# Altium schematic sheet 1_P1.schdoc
size 612 x 312 mm; Symbol: Sheet-Symbol_A4; Device: Sheet-Symbol_A4; @Project Name: TG-U1; Reviewed: EasyEDA; Part Number: JLCPCB-002; Drawn: EasyEDA; @Page Count: 1; @Update Date: 2024-12-23; @Create Date: 2024-12-20; @Schematic Name: Schematic1; @Page No: 1; @Page Name: P1; Company: EasyEDA.com; Version: V0.1; Page Size: A4; @Create Time: 16:03:04; @Update Time: 22:39:37; Title Block Position: 3; Width: 2362.2047244094488; Height: 1181.1023622047244; Region Start: 1; X Region Count: 6; Y Region Count: 4; Color: #660000; Blade Width: 10; @Board Name: Board1
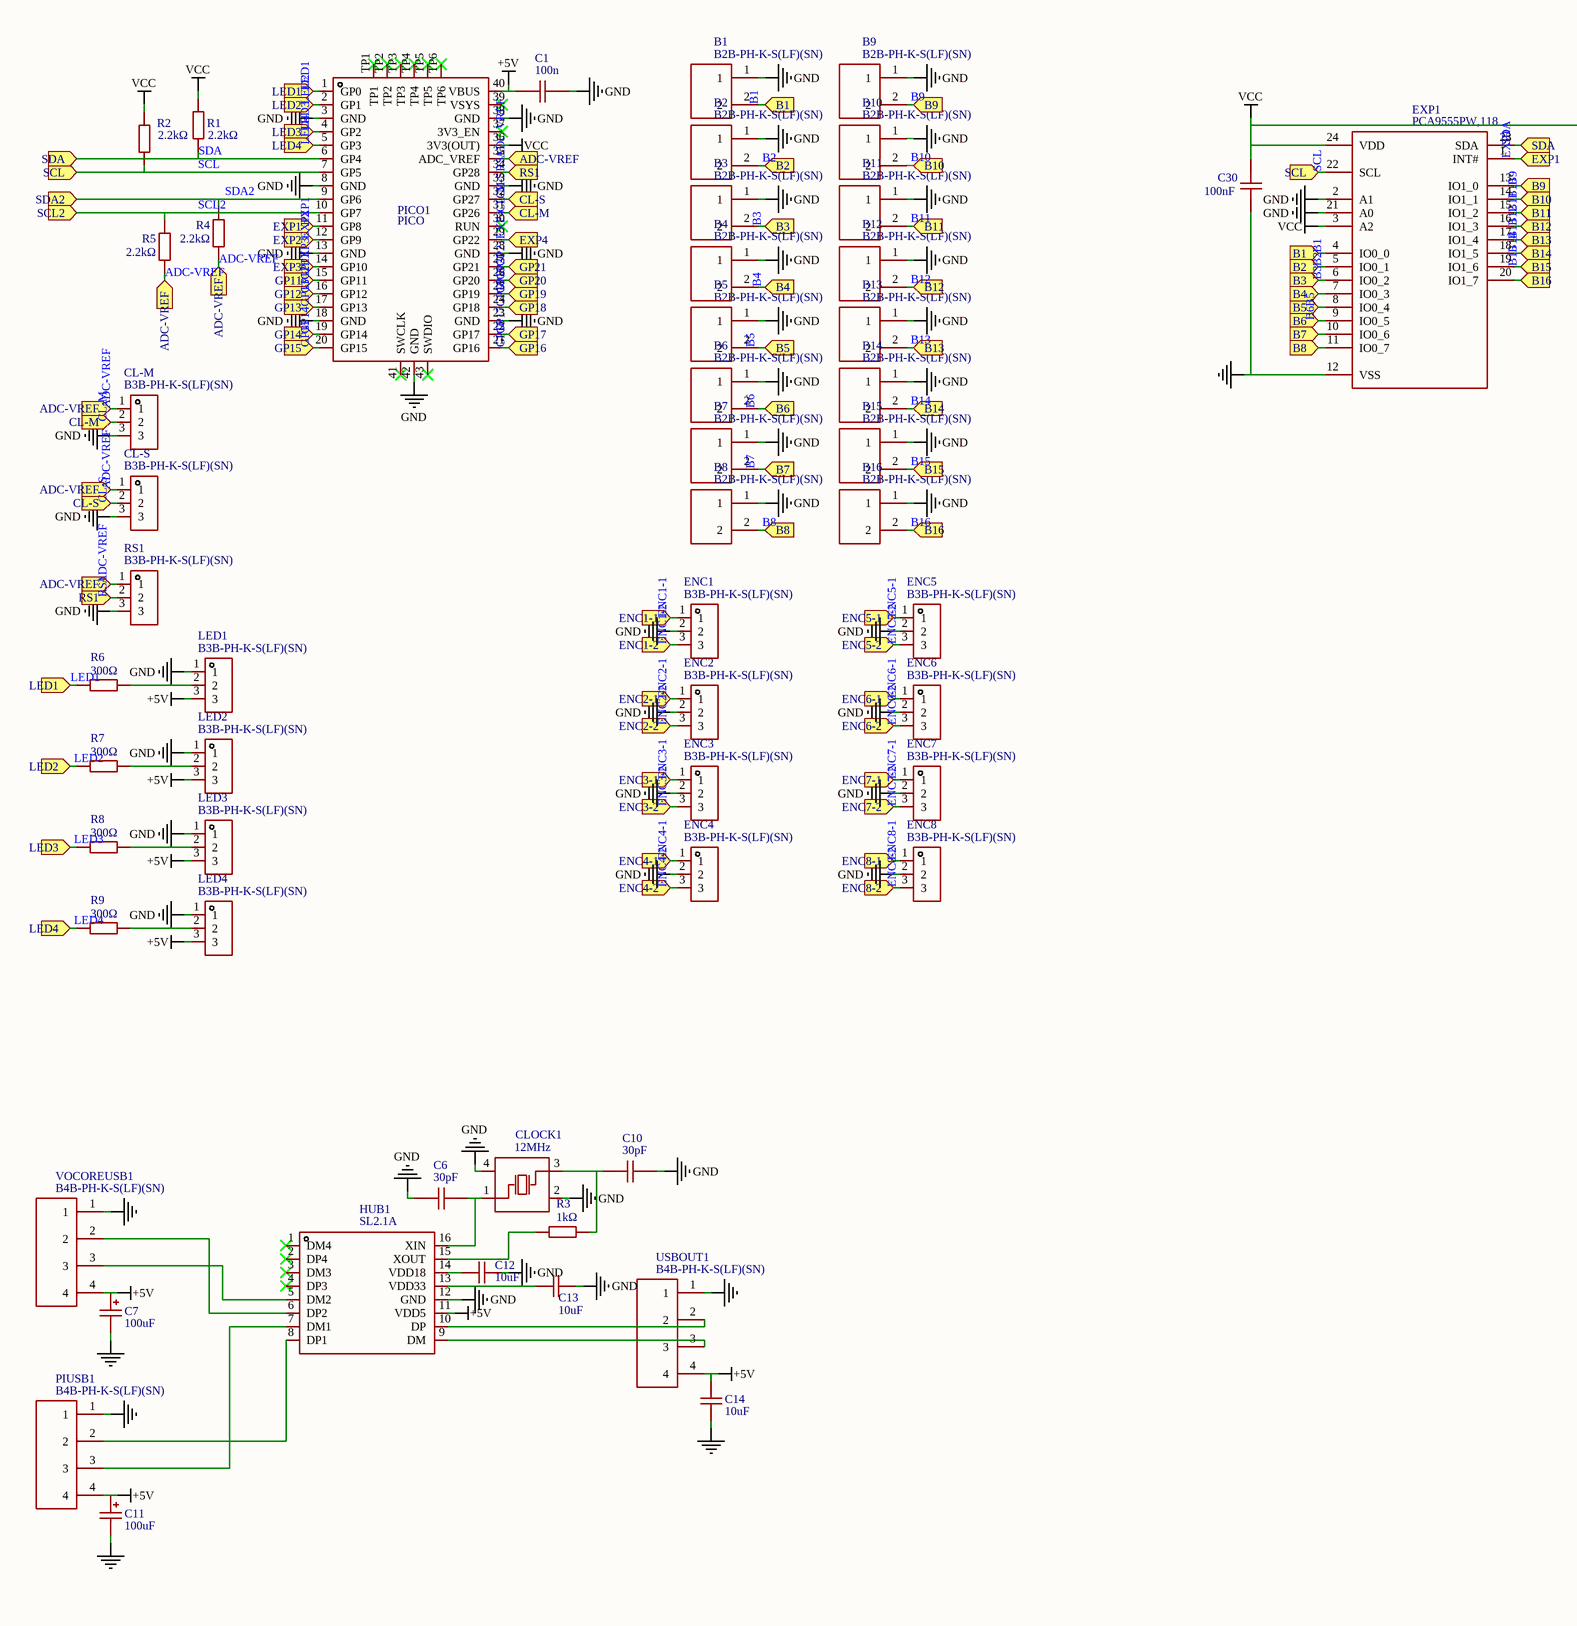
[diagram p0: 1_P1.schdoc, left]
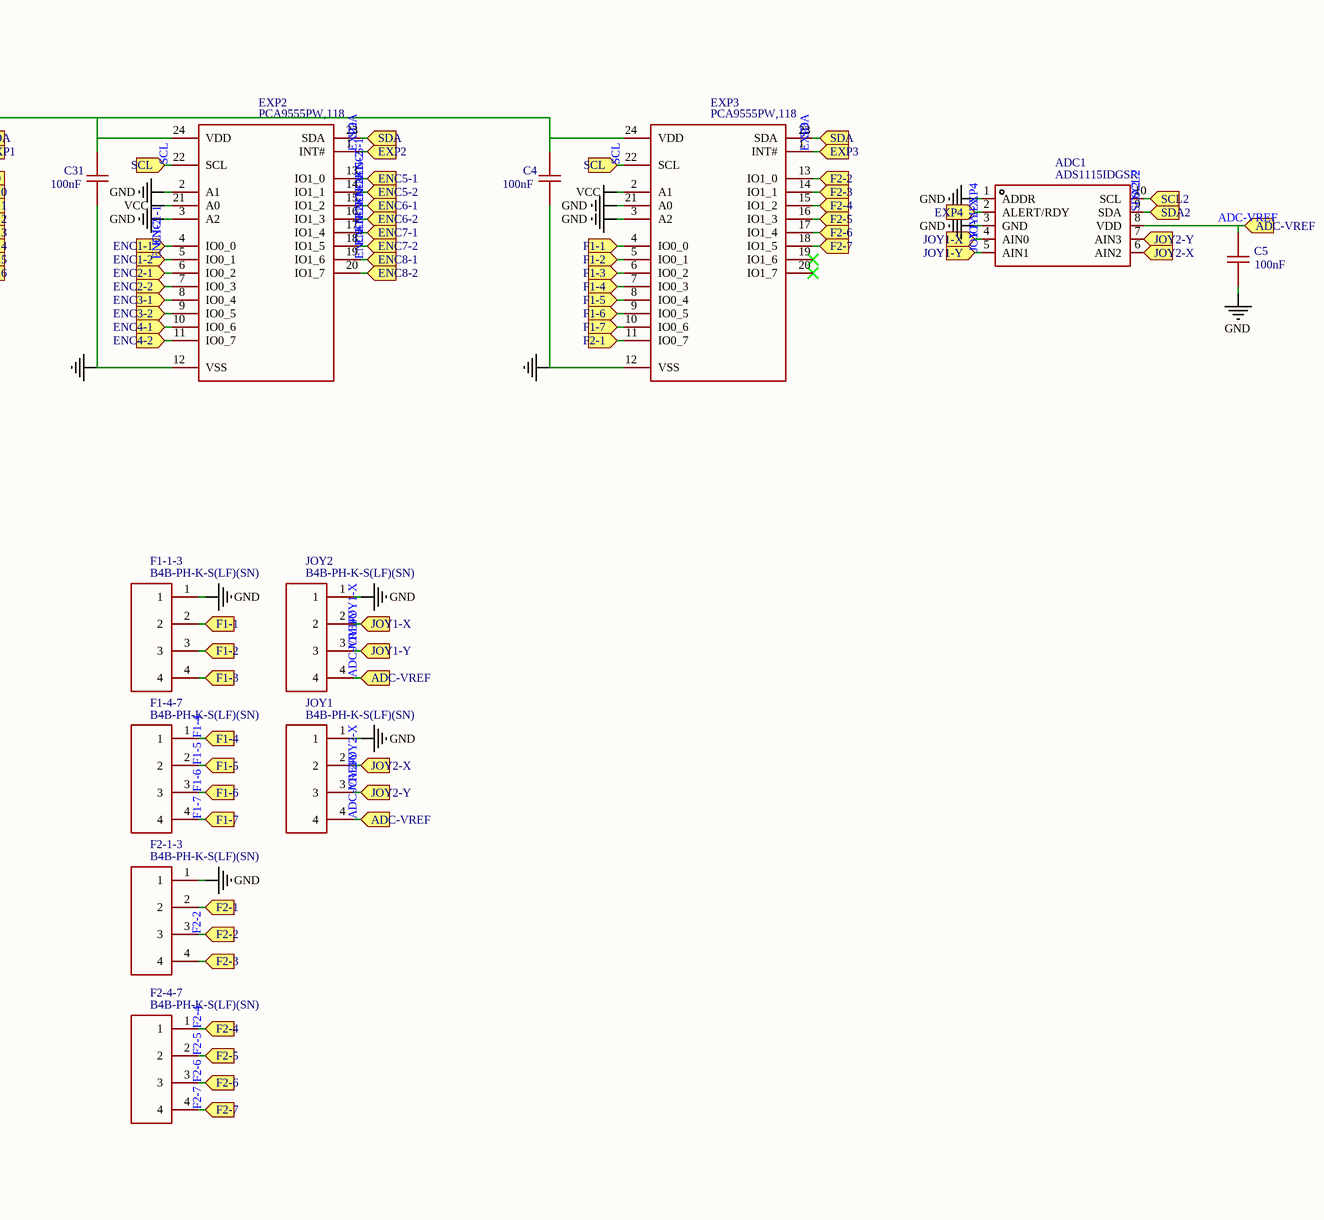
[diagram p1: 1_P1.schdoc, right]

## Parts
ADC1  ADS1115IDGSR  [MSOP-10_L3.0-W3.0-P0.50-LS5.0-BL]  (value not drawn)
B1  B2B-PH-K-S(LF)(SN)  [CONN-TH_B2B-PH-K-S]  (value not drawn)
B2  B2B-PH-K-S(LF)(SN)  [CONN-TH_B2B-PH-K-S]  (value not drawn)
B3  B2B-PH-K-S(LF)(SN)  [CONN-TH_B2B-PH-K-S]  (value not drawn)
B4  B2B-PH-K-S(LF)(SN)  [CONN-TH_B2B-PH-K-S]  (value not drawn)
B5  B2B-PH-K-S(LF)(SN)  [CONN-TH_B2B-PH-K-S]  (value not drawn)
B6  B2B-PH-K-S(LF)(SN)  [CONN-TH_B2B-PH-K-S]  (value not drawn)
B7  B2B-PH-K-S(LF)(SN)  [CONN-TH_B2B-PH-K-S]  (value not drawn)
B8  B2B-PH-K-S(LF)(SN)  [CONN-TH_B2B-PH-K-S]  (value not drawn)
B9  B2B-PH-K-S(LF)(SN)  [CONN-TH_B2B-PH-K-S]  (value not drawn)
B10  B2B-PH-K-S(LF)(SN)  [CONN-TH_B2B-PH-K-S]  (value not drawn)
B11  B2B-PH-K-S(LF)(SN)  [CONN-TH_B2B-PH-K-S]  (value not drawn)
B12  B2B-PH-K-S(LF)(SN)  [CONN-TH_B2B-PH-K-S]  (value not drawn)
B13  B2B-PH-K-S(LF)(SN)  [CONN-TH_B2B-PH-K-S]  (value not drawn)
B14  B2B-PH-K-S(LF)(SN)  [CONN-TH_B2B-PH-K-S]  (value not drawn)
B15  B2B-PH-K-S(LF)(SN)  [CONN-TH_B2B-PH-K-S]  (value not drawn)
B16  B2B-PH-K-S(LF)(SN)  [CONN-TH_B2B-PH-K-S]  (value not drawn)
C1  100n  [C0603]  (value not drawn)
C4  100nF  [C0603]  (value not drawn)
C5  100nF  [C0603]  (value not drawn)
C6  30pF  [C0603]  (value not drawn)
C7  100uF  [CAP-SMD_L3.5-W2.8]  (value not drawn)
C10  30pF  [C0603]  (value not drawn)
C11  100uF  [CAP-SMD_L3.5-W2.8]  (value not drawn)
C12  10uF  [C0402]  (value not drawn)
C13  10uF  [C0402]  (value not drawn)
C14  10uF  [C0402]  (value not drawn)
C30  100nF  [C0603]  (value not drawn)
C31  100nF  [C0603]  (value not drawn)
CL-M  B3B-PH-K-S(LF)(SN)  [CONN-TH_B3B-PH-K-S]  (value not drawn)
CL-S  B3B-PH-K-S(LF)(SN)  [CONN-TH_B3B-PH-K-S]  (value not drawn)
CLOCK1  12MHz  [OSC-SMD_4P-L3.2-W2.5-BL]  (value not drawn)
ENC1  B3B-PH-K-S(LF)(SN)  [CONN-TH_B3B-PH-K-S]  (value not drawn)
ENC2  B3B-PH-K-S(LF)(SN)  [CONN-TH_B3B-PH-K-S]  (value not drawn)
ENC3  B3B-PH-K-S(LF)(SN)  [CONN-TH_B3B-PH-K-S]  (value not drawn)
ENC4  B3B-PH-K-S(LF)(SN)  [CONN-TH_B3B-PH-K-S]  (value not drawn)
ENC5  B3B-PH-K-S(LF)(SN)  [CONN-TH_B3B-PH-K-S]  (value not drawn)
ENC6  B3B-PH-K-S(LF)(SN)  [CONN-TH_B3B-PH-K-S]  (value not drawn)
ENC7  B3B-PH-K-S(LF)(SN)  [CONN-TH_B3B-PH-K-S]  (value not drawn)
ENC8  B3B-PH-K-S(LF)(SN)  [CONN-TH_B3B-PH-K-S]  (value not drawn)
EXP1  PCA9555PW,118  [TSSOP-24_L7.8-W4.4-P0.65-LS6.4-BL]  (value not drawn)
EXP2  PCA9555PW,118  [TSSOP-24_L7.8-W4.4-P0.65-LS6.4-BL]  (value not drawn)
EXP3  PCA9555PW,118  [TSSOP-24_L7.8-W4.4-P0.65-LS6.4-BL]  (value not drawn)
F1-1-3  B4B-PH-K-S(LF)(SN)  [CONN-TH_B4B-PH-K-S]  (value not drawn)
F1-4-7  B4B-PH-K-S(LF)(SN)  [CONN-TH_B4B-PH-K-S]  (value not drawn)
F2-1-3  B4B-PH-K-S(LF)(SN)  [CONN-TH_B4B-PH-K-S]  (value not drawn)
F2-4-7  B4B-PH-K-S(LF)(SN)  [CONN-TH_B4B-PH-K-S]  (value not drawn)
HUB1  SL2.1A  [SOP-16_L10.0-W3.9-P1.27-LS6.0-BL]  (value not drawn)
JOY1  B4B-PH-K-S(LF)(SN)  [CONN-TH_B4B-PH-K-S]  (value not drawn)
JOY2  B4B-PH-K-S(LF)(SN)  [CONN-TH_B4B-PH-K-S]  (value not drawn)
LED1  B3B-PH-K-S(LF)(SN)  [CONN-TH_B3B-PH-K-S]  (value not drawn)
LED2  B3B-PH-K-S(LF)(SN)  [CONN-TH_B3B-PH-K-S]  (value not drawn)
LED3  B3B-PH-K-S(LF)(SN)  [CONN-TH_B3B-PH-K-S]  (value not drawn)
LED4  B3B-PH-K-S(LF)(SN)  [CONN-TH_B3B-PH-K-S]  (value not drawn)
PICO1  PICO  [COMM-SMD_L51.0-W21.0-P2.54_SC0916]  (value not drawn)
PIUSB1  B4B-PH-K-S(LF)(SN)  [CONN-TH_B4B-PH-K-S]  (value not drawn)
R1  2.2kΩ  [R0402]  (value not drawn)
R2  2.2kΩ  [R0402]  (value not drawn)
R3  1kΩ  [R0805]  (value not drawn)
R4  2.2kΩ  [R0402]  (value not drawn)
R5  2.2kΩ  [R0402]  (value not drawn)
R6  300Ω  [R0402]  (value not drawn)
R7  300Ω  [R0402]  (value not drawn)
R8  300Ω  [R0402]  (value not drawn)
R9  300Ω  [R0402]  (value not drawn)
RS1  B3B-PH-K-S(LF)(SN)  [CONN-TH_B3B-PH-K-S]  (value not drawn)
USBOUT1  B4B-PH-K-S(LF)(SN)  [CONN-TH_B4B-PH-K-S]  (value not drawn)
VOCOREUSB1  B4B-PH-K-S(LF)(SN)  [CONN-TH_B4B-PH-K-S]  (value not drawn)

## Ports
ADC-VREF (in), B1 (in), B2 (in), B3 (in), B4 (in), B5 (in), B6 (in), B7 (in), B8 (in), B9 (in), B10 (in), B11 (in), B12 (in), B13 (in), B14 (in), B15 (in), B16 (in), CL-M (in), CL-S (in), ENC1-1 (in), ENC1-2 (in), ENC2-1 (in), ENC2-2 (in), ENC3-1 (in), ENC3-2 (in), ENC4-1 (in), ENC4-2 (in), ENC5-1 (in), ENC5-2 (in), ENC6-1 (in), ENC6-2 (in), ENC7-1 (in), ENC7-2 (in), ENC8-1 (in), ENC8-2 (in), EXP1 (in), EXP2 (in), EXP3 (in), EXP4 (in), F1-1 (in), F1-2 (in), F1-3 (in), F1-4 (in), F1-5 (in), F1-6 (in), F1-7 (in), F2-1 (in), F2-2 (in), F2-3 (in), F2-4 (in), F2-5 (in), F2-6 (in), F2-7 (in), GP11 (in), GP12 (in), GP13 (in), GP14 (in), GP15 (in), GP16 (in), GP17 (in), GP18 (in), GP19 (in), GP20 (in), GP21 (in), JOY1-X (in), JOY1-Y (in), JOY2-X (in), JOY2-Y (in), LED1 (in), LED2 (in), LED3 (in), LED4 (in), RS1 (in), SCL2 (in), SCL (in), SDA2 (in), SDA (in)

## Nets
+5V: C1.2 C7.1 C11.1 C14.1 HUB1.11(VDD5) LED1.3 LED2.3 LED3.3 LED4.3 PICO1.40(VBUS) PIUSB1.4 USBOUT1.4 VOCOREUSB1.4
GND: ADC1.1(ADDR) ADC1.3(GND) B1.1 B2.1 B3.1 B4.1 B5.1 B6.1 B7.1 B8.1 B9.1 B10.1 B11.1 B12.1 B13.1 B14.1 B15.1 B16.1 C1.1 C4.1 C5.1 C6.1 C7.2 C10.2 C11.2 C12.2 C13.2 C14.2 C30.1 C31.1 CL-M.3 CL-S.3 CLOCK1.2(GND) CLOCK1.4(GND) ENC1.2 ENC2.2 ENC3.2 ENC4.2 ENC5.2 ENC6.2 ENC7.2 ENC8.2 EXP1.2(A1) EXP1.12(VSS) EXP1.21(A0) EXP2.2(A1) EXP2.3(A2) EXP2.12(VSS) EXP3.3(A2) EXP3.12(VSS) EXP3.21(A0) F1-1-3.1 F2-1-3.1 HUB1.12(GND) JOY1.1 JOY2.1 LED1.1 LED2.1 LED3.1 LED4.1 PICO1.3(GND) PICO1.8(GND) PICO1.13(GND) PICO1.18(GND) PICO1.23(GND) PICO1.28(GND) PICO1.33(GND) PICO1.38(GND) PICO1.42(GND) PIUSB1.1 RS1.3 USBOUT1.1 VOCOREUSB1.1
VCC: C4.2 C30.2 C31.2 EXP1.3(A2) EXP1.24(VDD) EXP2.21(A0) EXP2.24(VDD) EXP3.2(A1) EXP3.24(VDD) PICO1.36(3V3(OUT)) R1.1 R2.1
ADC-VREF: ADC1.8(VDD) C5.2 CL-M.1 CL-S.1 JOY1.4 JOY2.4 PICO1.35(ADC_VREF) R4.2 R5.2 RS1.1 ; port ADC-VREF
B1: B1.2 EXP1.4(IO0_0) ; port B1
B2: B2.2 EXP1.5(IO0_1) ; port B2
B3: B3.2 EXP1.6(IO0_2) ; port B3
B4: B4.2 EXP1.7(IO0_3) ; port B4
B5: B5.2 EXP1.8(IO0_4) ; port B5
B6: B6.2 EXP1.9(IO0_5) ; port B6
B7: B7.2 EXP1.10(IO0_6) ; port B7
B8: B8.2 EXP1.11(IO0_7) ; port B8
B9: B9.2 EXP1.13(IO1_0) ; port B9
B10: B10.2 EXP1.14(IO1_1) ; port B10
B11: B11.2 EXP1.15(IO1_2) ; port B11
B12: B12.2 EXP1.16(IO1_3) ; port B12
B13: B13.2 EXP1.17(IO1_4) ; port B13
B14: B14.2 EXP1.18(IO1_5) ; port B14
B15: B15.2 EXP1.19(IO1_6) ; port B15
B16: B16.2 EXP1.20(IO1_7) ; port B16
CL-M: CL-M.2 PICO1.31(GP26) ; port CL-M
CL-S: CL-S.2 PICO1.32(GP27) ; port CL-S
ENC1-1: ENC1.1 EXP2.4(IO0_0) ; port ENC1-1
ENC1-2: ENC1.3 EXP2.5(IO0_1) ; port ENC1-2
ENC2-1: ENC2.1 EXP2.6(IO0_2) ; port ENC2-1
ENC2-2: ENC2.3 EXP2.7(IO0_3) ; port ENC2-2
ENC3-1: ENC3.1 EXP2.8(IO0_4) ; port ENC3-1
ENC3-2: ENC3.3 EXP2.9(IO0_5) ; port ENC3-2
ENC4-1: ENC4.1 EXP2.10(IO0_6) ; port ENC4-1
ENC4-2: ENC4.3 EXP2.11(IO0_7) ; port ENC4-2
ENC5-1: ENC5.1 EXP2.13(IO1_0) ; port ENC5-1
ENC5-2: ENC5.3 EXP2.14(IO1_1) ; port ENC5-2
ENC6-1: ENC6.1 EXP2.15(IO1_2) ; port ENC6-1
ENC6-2: ENC6.3 EXP2.16(IO1_3) ; port ENC6-2
ENC7-1: ENC7.1 EXP2.17(IO1_4) ; port ENC7-1
ENC7-2: ENC7.3 EXP2.18(IO1_5) ; port ENC7-2
ENC8-1: ENC8.1 EXP2.19(IO1_6) ; port ENC8-1
ENC8-2: ENC8.3 EXP2.20(IO1_7) ; port ENC8-2
EXP1: EXP1.1(INT#) PICO1.11(GP8) ; port EXP1
EXP2: EXP2.1(INT#) PICO1.12(GP9) ; port EXP2
EXP3: EXP3.1(INT#) PICO1.14(GP10) ; port EXP3
EXP4: ADC1.2(ALERT/RDY) PICO1.29(GP22) ; port EXP4
F1-1: EXP3.4(IO0_0) F1-1-3.2 ; port F1-1
F1-2: EXP3.5(IO0_1) F1-1-3.3 ; port F1-2
F1-3: EXP3.6(IO0_2) F1-1-3.4 ; port F1-3
F1-4: EXP3.7(IO0_3) F1-4-7.1 ; port F1-4
F1-5: EXP3.8(IO0_4) F1-4-7.2 ; port F1-5
F1-6: EXP3.9(IO0_5) F1-4-7.3 ; port F1-6
F1-7: EXP3.10(IO0_6) F1-4-7.4 ; port F1-7
F2-1: EXP3.11(IO0_7) F2-1-3.2 ; port F2-1
F2-2: EXP3.13(IO1_0) F2-1-3.3 ; port F2-2
F2-3: EXP3.14(IO1_1) F2-1-3.4 ; port F2-3
F2-4: EXP3.15(IO1_2) F2-4-7.1 ; port F2-4
F2-5: EXP3.16(IO1_3) F2-4-7.2 ; port F2-5
F2-6: EXP3.17(IO1_4) F2-4-7.3 ; port F2-6
F2-7: EXP3.18(IO1_5) F2-4-7.4 ; port F2-7
GP11: PICO1.15(GP11) ; port GP11
GP12: PICO1.16(GP12) ; port GP12
GP13: PICO1.17(GP13) ; port GP13
GP14: PICO1.19(GP14) ; port GP14
GP15: PICO1.20(GP15) ; port GP15
GP16: PICO1.21(GP16) ; port GP16
GP17: PICO1.22(GP17) ; port GP17
GP18: PICO1.24(GP18) ; port GP18
GP19: PICO1.25(GP19) ; port GP19
GP20: PICO1.26(GP20) ; port GP20
GP21: PICO1.27(GP21) ; port GP21
JOY1-X: ADC1.4(AIN0) JOY2.2 ; port JOY1-X
JOY1-Y: ADC1.5(AIN1) JOY2.3 ; port JOY1-Y
JOY2-X: ADC1.6(AIN2) JOY1.2 ; port JOY2-X
JOY2-Y: ADC1.7(AIN3) JOY1.3 ; port JOY2-Y
LED1: PICO1.1(GP0) R6.1 ; port LED1
LED2: PICO1.2(GP1) R7.1 ; port LED2
LED3: PICO1.4(GP2) R8.1 ; port LED3
LED4: PICO1.5(GP3) R9.1 ; port LED4
RS1: PICO1.34(GP28) RS1.2 ; port RS1
SCL: EXP1.22(SCL) EXP2.22(SCL) EXP3.22(SCL) PICO1.7(GP5) R2.2 ; port SCL
SCL2: ADC1.10(SCL) PICO1.10(GP7) R5.1 ; port SCL2
SDA: EXP1.23(SDA) EXP2.23(SDA) EXP3.23(SDA) PICO1.6(GP4) R1.2 ; port SDA
SDA2: ADC1.9(SDA) PICO1.9(GP6) R4.1 ; port SDA2
NetC6_2: C6.2 CLOCK1.1(OSC1) HUB1.16(XIN)
NetC10_1: C10.1 CLOCK1.3(OSC2) R3.2
NetC12_1: C12.1 HUB1.14(VDD18)
NetC13_1: C13.1 HUB1.13(VDD33)
NetHUB1_5: HUB1.5(DM2) VOCOREUSB1.3
NetHUB1_6: HUB1.6(DP2) VOCOREUSB1.2
NetHUB1_7: HUB1.7(DM1) PIUSB1.3
NetHUB1_8: HUB1.8(DP1) PIUSB1.2
NetHUB1_9: HUB1.9(DM) USBOUT1.3
NetHUB1_10: HUB1.10(DP) USBOUT1.2
NetHUB1_15: HUB1.15(XOUT) R3.1
NetLED1_2: LED1.2 R6.2
NetLED2_2: LED2.2 R7.2
NetLED3_2: LED3.2 R8.2
NetLED4_2: LED4.2 R9.2

Not connected (* = marked no-connect by the designer): EXP3 19(IO1_6)* 20(IO1_7)*; HUB1 1(DM4)* 2(DP4)* 3(DM3)* 4(DP3)*; PICO1 30(RUN)* 37(3V3_EN)* 39(VSYS)* 41(SWCLK)* 43(SWDIO)* TP1* TP2* TP3* TP4* TP5* TP6*

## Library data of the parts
ADC1 = ADS1115IDGSR: Manufacturer: TI(德州仪器); Convert to PCB: yes
B1-B16 = B2B-PH-K-S(LF)(SN): Manufacturer: JST; Convert to PCB: yes
C1 = 100n: Convert to PCB: yes
C4 C5 C30 C31 = 100nF: Manufacturer: SAMWHA(三和); Manufacturer Part: CS1608X7R104K500NRB; Convert to PCB: yes
C6 C10 = 30pF: Manufacturer: CCTC(三环); Manufacturer Part: TCC0603COG300J500CT; Convert to PCB: yes
C7 C11 = 100uF: Manufacturer: AVX; Manufacturer Part: TAJB107K006RNJ; Paste Type: base; Convert to PCB: yes
C12-C14 = 10uF: Manufacturer Part: CL05A106MQ5NUNC; Manufacturer: SAMSUNG; Paste Type: base; Convert to PCB: yes
CL-M CL-S ENC1-ENC8 LED1-LED4 RS1 = B3B-PH-K-S(LF)(SN): Manufacturer: JST; Convert to PCB: yes
CLOCK1 = 12MHz: Manufacturer: YXC; Manufacturer Part: X322512MSB4SI; Paste Type: base; Convert to PCB: yes
EXP1-EXP3 = PCA9555PW,118: Manufacturer: NXP(恩智浦); Convert to PCB: yes
F1-1-3 F1-4-7 F2-1-3 F2-4-7 JOY1 JOY2 PIUSB1 USBOUT1 VOCOREUSB1 = B4B-PH-K-S(LF)(SN): Manufacturer: JST; Convert to PCB: yes
HUB1 = SL2.1A: Manufacturer: CoreChips; Paste Type: expand; Convert to PCB: yes
PICO1 = PICO: Manufacturer: Raspberry Pi(树莓派); Convert to PCB: yes
R1 R2 R4 R5 = 2.2kΩ: Manufacturer: YAGEO(国巨); Manufacturer Part: AC0402FR-072K2L; Convert to PCB: yes
R3 = 1kΩ: Manufacturer: FH(风华); Manufacturer Part: RS-05K102JT; Convert to PCB: yes
R6-R9 = 300Ω: Manufacturer: YAGEO(国巨); Manufacturer Part: RC0402FR-07300RL; Convert to PCB: yes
